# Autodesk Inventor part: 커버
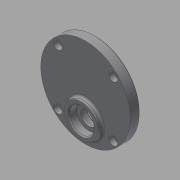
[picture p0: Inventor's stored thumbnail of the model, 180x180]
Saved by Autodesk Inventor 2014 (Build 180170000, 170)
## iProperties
Created: 2015-07
Part Number: 커버
Material: Generic
Document SubType Name: Modeling
Designer: Administrator
Density: 1 g/cm^3
Appearance: Default
Author: Administrator
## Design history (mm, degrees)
sketch "스케치1"
  geometry: C1 r 40 at (0, 0); 1 further point
  constraints: 1 centre point, 1 coincident
  dimensions: "d0" = 80 diameter of C1
extrude "돌출1" new body sketch "스케치1" distance "d1" = 9; taper "d2" = 0 deg
sketch "스케치2"
  geometry: C1 r 40 at (0, 0) reference; C2 r 15 at (0, -20)
  constraints: 1 centre point, 1 vertical alignment
  dimensions: "d3" = 20 distance of C1.centre C2.centre; "d4" = 30 diameter of C2
extrude "돌출2" join sketch "스케치2" distance "d5" = 4; taper "d6" = 0 deg
sketch "스케치3"
  geometry: C1 r 40 at (0, 0) reference; C2 r 14 at (0, -11); C3 r 14 at (0, 20)
  constraints: 2 centre point, 2 vertical alignment
  dimensions: "d7" = 11 distance of C1.centre C2.centre; "d8" = 20 distance of C1.centre C3.centre; "d9" = 28 diameter of C3; "d10" = 28 diameter of C2
extrude "돌출3" join sketch "스케치3" distance "d11" = 3; taper "d12" = 0 deg
sketch "스케치4"
  geometry: C1 r 15 at (0, 0) reference; C2 r 11 at (0, 0); 1 further point
  constraints: 1 centre point, 1 coincident
  dimensions: "d13" = 22 diameter of C2
extrude "돌출4" cut sketch "스케치4" distance "d14" = 7; taper "d15" = 0 deg
sketch "스케치5"
  geometry: C1 r 14 at (0, 0) reference; C2 r 11 at (0, 0); 1 further point
  constraints: 1 centre point, 1 coincident
  dimensions: "d16" = 22 diameter of C2
extrude "돌출5" cut sketch "스케치5" distance "d17" = 7; taper "d18" = 0 deg
sketch "스케치6"
  geometry: C1 r 11 at (0, 0) reference; C2 r 7.5 at (0, 0); 1 further point
  constraints: 1 centre point, 1 coincident
  dimensions: "d19" = 15 diameter of C2
extrude "돌출6" cut sketch "스케치6" distance "d20" = 2; taper "d21" = 0 deg
sketch "스케치7"
  geometry: C1 r 14 at (0, 0) reference; C2 r 11 at (0, 0); 1 further point
  constraints: 1 centre point, 1 coincident
  dimensions: "d22" = 22 diameter of C2
extrude "돌출7" cut sketch "스케치7" distance "d23" = 7; taper "d24" = 0 deg
sketch "스케치8"
  geometry: C1 r 9 at (0, 0); 2 further points
  constraints: 1 centre point, 1 coincident, 1 vertical alignment
  dimensions: "d25" = 18 diameter of C1
extrude "돌출8" cut sketch "스케치8" distance "d26" = 1; taper "d27" = 0 deg
sketch "스케치9"
  geometry: L1 (0, 0)-(28.284, 28.284); L2 (0, 0)-(35, 0); C1 r 4 at (24.749, 24.749); A1 r 35 centre (0, 0) between (35, 0) and (24.749, 24.749)
  constraints: 4 end point, 2 centre point, 2 point on circle, 1 coincident, 1 horizontal, 1 point on line, 2 other
  dimensions: "d28" = 70 diameter of A1; "d29" = 45 deg angle of L2 L1; "d30" = 8 diameter of C1
extrude "돌출9" cut sketch "스케치9" distance "d31" = 4.4; taper "d32" = 0 deg
sketch "스케치10"
  geometry: C1 r 4 at (0, 0) reference; C2 r 2.25 at (0, 0); 1 further point
  constraints: 1 centre point, 1 coincident
  dimensions: "d33" = 4.5 diameter of C2
extrude "돌출10" cut sketch "스케치10" stored distance "d34" = 4.4; taper "d35" = 0 deg
chamfer "모따기1" distance "d39" = 1; stored, may be unused: second distance "d40" = 2, angle "d41" = 45 deg
fillet "모깎기1" dims "d42" = 0.3
fillet "모깎기2" dims "d43" = 2
chamfer "모따기2" distance "d44" = 1; stored, may be unused: second distance "d45" = 2, angle "d46" = 45 deg
fillet "모깎기3" dims "d47" = 2
node "솔리드1"
pattern_circular "원형 패턴1" dims angle "d37" = 360 deg
